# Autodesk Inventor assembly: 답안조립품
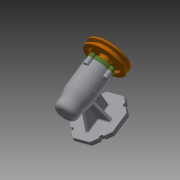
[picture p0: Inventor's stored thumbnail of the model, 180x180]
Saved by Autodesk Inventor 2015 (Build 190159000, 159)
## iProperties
Created: 2019-12
Part Number: 답안조립품
Document SubType Name: Assembly
Designer: now
Author: now
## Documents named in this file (12)
- C:\Users\now\Desktop\12221김찬희\491204V1073\답안조립품.iam
- C:\Users\now\Desktop\12221김찬희\491204V1073\Ű 5 x 5 x 16.ipt
- C:\Users\now\Desktop\12221김찬희\491204V1073\V벨트풀리.ipt
- C:\Users\now\Desktop\12221김찬희\491204V1073\멈춤나사 M3.ipt
- C:\Users\now\Desktop\12221김찬희\491204V1073\베어링 6004.ipt
- C:\Users\now\Desktop\12221김찬희\491204V1073\베어링 51202.ipt
- C:\Users\now\Desktop\12221김찬희\491204V1073\볼트 M4.ipt
- C:\Users\now\Desktop\12221김찬희\491204V1073\부품1.ipt
- C:\Users\now\Desktop\12221김찬희\491204V1073\어댑터슬리브.ipt
- C:\Users\now\Desktop\12221김찬희\491204V1073\오일 실.ipt
- C:\Users\now\Desktop\12221김찬희\491204V1073\축.ipt
- C:\Users\now\Desktop\12221김찬희\491204V1073\커버.ipt
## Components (2 placed, 2 different names)
1. Ű 5 x 5 x 16:1 — 각도:1, 각도:2
2. V벨트풀리:1 — 각도:2
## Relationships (2: Angle 2)
- 각도:1 [Angle]: Ű 5 x 5 x 16:1
- 각도:2 [Angle]: Ű 5 x 5 x 16:1 ↔ V벨트풀리:1
